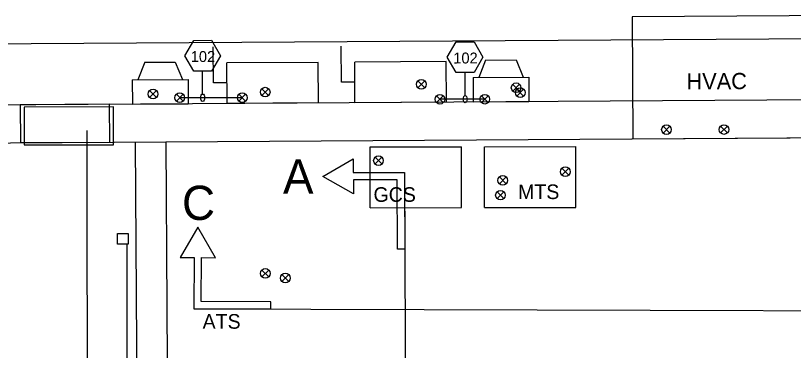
# Model space of a CAD drawing. Extents: x -2.6 to 16.3, y -2.7 to 7.5.
# Drawn here: x 3.72 to 10.11, y 4.51 to 7.26 of the extents above; entities that cross this region are included whole.
import ezdxf

# ---------------------------------------------------------------- set-up
doc = ezdxf.new("R2010")
doc.units = 0
for name, color, linetype in [('HS_Concrete_Object', 7, 'Continuous'), ('HS_Dimensions_and_Text', 7, 'Continuous'), ('HS_Electrical_Conduit', 7, 'Continuous'), ('HS_Electrical_Devices', 7, 'Continuous'), ('HS_Electrical_Enclosure', 7, 'Continuous'), ('HS_Miscellaneous', 7, 'Continuous'), ('HS_Pattern_and_Hatching-ILTollway', 7, 'Continuous'), ('SH_General_Details', 7, 'Continuous')]:
    doc.layers.add(name, color=color, linetype=linetype)

msp = doc.modelspace()

# ---------------------------------------------------------------- linework, layer by layer
at = {"layer": 'HS_Concrete_Object'}
for points in [[(10.5072, 6.2572), (10.5009, 7.2572), (8.7821, 7.2463), (8.7885, 6.2463)], [(15.9556, 7.1018), (-0.0446, 6.9998), (0, 0), (16.0002, 0.1019)]]:
    msp.add_lwpolyline(points, close=True, dxfattribs=at)
for points in [[(15.4629, 5.9473), (15.4588, 6.5986), (0.4591, 6.5025), (0.4974, 0.5032), (0.9916, 0.5063)], [(0.7399, 0.7823), (0.7054, 6.1941), (15.1483, 6.2872)], [(4.7053, 6.2172), (4.7398, 0.8078)], [(4.9553, 6.2188), (4.9898, 0.8094)]]:
    msp.add_lwpolyline(points, dxfattribs=at)
at = {"layer": 'HS_Dimensions_and_Text'}
for points in [[(6.2445, 5.9363), (6.4939, 6.0817), (6.4943, 5.9674), (6.9143, 5.9691), (6.917, 5.3391), (6.857, 5.3389), (6.8546, 5.9089), (6.4946, 5.9074), (6.4951, 5.793)], [(5.219, 5.5197), (5.074, 5.2701), (5.1883, 5.2697), (5.1871, 4.8497), (5.8171, 4.848), (5.8173, 4.908), (5.2473, 4.9096), (5.2483, 5.2696), (5.3626, 5.2693)]]:
    msp.add_lwpolyline(points, close=True, dxfattribs=at)
for points in [[(6.9145, 5.9388), (6.9345, 1.2436)], [(5.2174, 4.8497), (14.4996, 4.8233)]]:
    msp.add_lwpolyline(points, dxfattribs=at)
at = {"layer": 'HS_Electrical_Conduit'}
for p, q in [((7.8587, 6.6366), (7.8024, 6.6922)), ((7.8027, 6.6363), (7.8583, 6.6925))]:
    msp.add_line(p, q, dxfattribs=at)
msp.add_circle((7.8305, 6.6644), 0.0396, dxfattribs=at)
at = {"layer": 'HS_Electrical_Devices'}
for p, q in [((5.2582, 6.6128), (5.258, 6.8006)), ((7.412, 6.6006), (7.4119, 6.7884)), ((7.0805, 6.6649), (7.0246, 6.7209)), ((7.0246, 6.6649), (7.0805, 6.7209)), ((4.8792, 6.5847), (4.8233, 6.6407)), ((4.8233, 6.5847), (4.8792, 6.6407)), ((5.7995, 6.6006), (5.7436, 6.6565)), ((5.7436, 6.6006), (5.7995, 6.6565)), ((7.8921, 6.5962), (7.8361, 6.6522)), ((7.8361, 6.5962), (7.8921, 6.6522)), ((5.0985, 6.5544), (5.0426, 6.6104)), ((5.0426, 6.5544), (5.0985, 6.6104)), ((5.5831, 6.5829), (5.0706, 6.5824)), ((5.5551, 6.5549), (5.611, 6.6109)), ((5.611, 6.5549), (5.5551, 6.6108)), ((7.2328, 6.5422), (7.1769, 6.5982)), ((7.1769, 6.5422), (7.2328, 6.5982)), ((7.6012, 6.5426), (7.5452, 6.5985)), ((7.5452, 6.5426), (7.6012, 6.5985)), ((7.5732, 6.5705), (7.2048, 6.5702)), ((9.0919, 6.2928), (9.036, 6.3487)), ((9.036, 6.2928), (9.0919, 6.3487)), ((9.5637, 6.2932), (9.5078, 6.3492)), ((9.5078, 6.2932), (9.5637, 6.3492)), ((6.6327, 6.1794), (7.3827, 6.1801)), ((6.6331, 5.6794), (6.6327, 6.1794)), ((7.3831, 5.6801), (7.3827, 6.1801)), ((7.5701, 6.1803), (8.3201, 6.181)), ((7.5706, 5.6803), (7.5701, 6.1803)), ((8.3206, 5.681), (8.3201, 6.181)), ((6.729, 6.0385), (6.673, 6.0944)), ((6.673, 6.0385), (6.729, 6.0944)), ((8.2614, 5.9471), (8.2055, 6.003)), ((8.2055, 5.9471), (8.2614, 6.003)), ((7.7486, 5.8763), (7.6926, 5.9322)), ((7.6926, 5.8763), (7.7486, 5.9322)), ((7.7298, 5.7546), (7.6738, 5.8105)), ((7.6738, 5.7546), (7.7298, 5.8105)), ((7.5706, 5.6803), (8.3206, 5.681)), ((6.6331, 5.6794), (7.3831, 5.6801)), ((4.6351, 5.3815), (4.6362, 4.1004)), ((5.8009, 5.1121), (5.7449, 5.1681)), ((5.7449, 5.1121), (5.8009, 5.1681)), ((5.9647, 5.0742), (5.9087, 5.1301)), ((5.9087, 5.0742), (5.9646, 5.1301))]:
    msp.add_line(p, q, dxfattribs=at)
for points in [[(5.3308, 7.0538), (5.4041, 6.9273), (5.3311, 6.8006), (5.1849, 6.8005), (5.1117, 6.927), (5.1847, 7.0537)], [(7.4847, 7.0417), (7.5579, 6.9151), (7.485, 6.7884), (7.3388, 6.7883), (7.2656, 6.9148), (7.3385, 7.0415)], [(4.5606, 5.4679), (4.6471, 5.468), (4.6472, 5.3815), (4.5607, 5.3814)]]:
    msp.add_lwpolyline(points, close=True, dxfattribs=at)
msp.add_lwpolyline([(5.0645, 3.6124), (4.3141, 3.6117), (4.3116, 6.3146)], dxfattribs=at)
for centre in [(7.0526, 6.6929), (4.8513, 6.6127), (5.7715, 6.6286), (7.8641, 6.6242), (5.0706, 6.5824), (5.5831, 6.5829), (7.2048, 6.5702), (7.5732, 6.5705), (9.0639, 6.3208), (9.5357, 6.3212), (6.701, 6.0664), (8.2334, 5.9751), (7.7206, 5.9043), (7.7018, 5.7825), (5.7729, 5.1401), (5.9367, 5.1021)]:
    msp.add_circle(centre, 0.0396, dxfattribs=at)
for centre in [(5.2582, 6.5826), (7.4121, 6.5704)]:
    msp.add_ellipse(centre, major_axis=(0, 0.0302), ratio=0.534795, dxfattribs=at)
at = {"layer": 'HS_Electrical_Enclosure'}
for p, q in [((5.3465, 6.7036), (5.3446, 6.9998)), ((6.3965, 6.7102), (6.3946, 7.0065)), ((6.206, 6.8728), (5.4561, 6.8681)), ((5.4582, 6.5346), (5.4561, 6.8681)), ((6.2082, 6.5394), (6.206, 6.8728)), ((7.256, 6.8795), (6.506, 6.8748)), ((6.5082, 6.5413), (6.506, 6.8748)), ((7.2582, 6.546), (7.256, 6.8795)), ((7.5801, 6.8913), (7.5236, 6.7478)), ((7.5801, 6.8913), (7.8301, 6.8929)), ((7.8301, 6.8929), (7.8883, 6.7501)), ((5.4571, 6.7043), (5.3465, 6.7036)), ((6.5071, 6.7109), (6.3965, 6.7102)), ((7.4774, 6.7475), (7.9345, 6.7504)), ((7.4774, 6.7475), (7.4787, 6.5475)), ((7.9345, 6.7504), (7.9358, 6.5504)), ((6.2082, 6.5394), (5.4582, 6.5346)), ((7.2582, 6.546), (6.5082, 6.5413)), ((7.4787, 6.5475), (7.9358, 6.5504))]:
    msp.add_line(p, q, dxfattribs=at)
at = {"layer": 'HS_Miscellaneous'}
msp.add_lwpolyline([(3.7948, 6.1959), (4.5281, 6.1966), (4.5278, 6.5064), (3.7945, 6.5057)], close=True, dxfattribs=at)
at = {"layer": 'HS_Pattern_and_Hatching-ILTollway'}
for points in [[(3.7636, 6.2138), (4.4969, 6.2185), (4.495, 6.5283), (3.7616, 6.5237)], [(4.495, 6.5283), (3.7616, 6.5236), (3.7636, 6.2136), (4.4969, 6.2183)], [(4.5278, 6.5064), (3.7945, 6.5057), (3.7948, 6.1956), (4.5281, 6.1963)]]:
    msp.add_lwpolyline(points, close=True, dxfattribs=at)
at = {"layer": 'SH_General_Details'}
for p, q in [((4.784, 6.8734), (4.7275, 6.7299)), ((4.784, 6.8734), (5.034, 6.875)), ((5.034, 6.875), (5.0922, 6.7322)), ((4.6813, 6.7296), (5.1384, 6.7325)), ((4.6813, 6.7296), (4.6826, 6.5296)), ((5.1384, 6.7325), (5.1397, 6.5325)), ((4.6826, 6.5296), (5.1397, 6.5325))]:
    msp.add_line(p, q, dxfattribs=at)

# ---------------------------------------------------------------- texts
at = {"layer": 'HS_Dimensions_and_Text'}
for s, height, rotation, p in [('HVAC', 0.13333, 0.36505, (9.2287, 6.65)), ('A', 0.2808, 0.24414, (5.9175, 5.7945)), ('C', 0.2808, 359.8371, (5.0884, 5.5796))]:
    msp.add_text(s, height=height, rotation=rotation, dxfattribs=at).set_placement(p)
at = {"layer": 'HS_Electrical_Devices'}
for s, height, p in [('102', 0.08959, (5.1609, 6.8757)), ('102', 0.08959, (7.3148, 6.8635)), ('MTS', 0.12, (7.8461, 5.75)), ('GCS', 0.12, (6.66, 5.7276)), ('ATS', 0.12, (5.2579, 4.6857))]:
    msp.add_text(s, height=height, rotation=0.05234, dxfattribs=at).set_placement(p)

doc.saveas('drawing.dxf')
